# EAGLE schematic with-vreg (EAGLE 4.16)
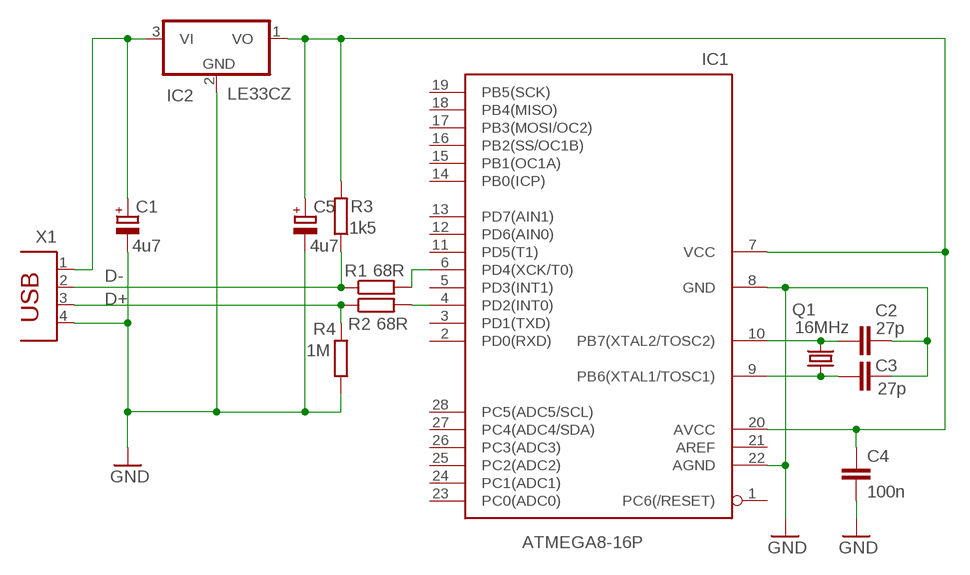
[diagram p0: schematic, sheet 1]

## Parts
C1  4u7  CPOL-EUE2-5  [E2-5]
C2  27p  C-EU025-024X044  [C025-024X044]
C3  27p  C-EU025-024X044  [C025-024X044]
C4  100n  C-EU025-024X044  [C025-024X044]
C5  4u7  CPOL-EUE2-5  [E2-5]
IC1  ATMEGA8-16P  [DIL28-3]
IC2  LE33CZ  78L05Z  [TO92]
Q1  16MHz  CRYTALHC49U-V  [HC49U-V]
R1  68R  R-EU_0207/10  [0207/10]
R2  68R  R-EU_0207/10  [0207/10]
R3  1k5  R-EU_0207/10  [0207/10]
R4  1M  R-EU_0207/10  [0207/10]
X1  PN61729  [PN61729]

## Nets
D+: R2.1 R4.2 X1.3
D-: R1.1 R3.1 X1.2
GND: C1.- C2.2 C3.2 C4.2 C5.- IC1.8(GND) IC1.22(AGND) IC2.2(GND) R4.1 X1.4
N$1: IC1.6(PD4(XCK/T0)) R1.2
N$2: IC1.4(PD2(INT0)) R2.2
N$3: C1.+ IC2.3(VI) X1.1
N$9: C3.1 IC1.9(PB6(XTAL1/TOSC1)) Q1.1
N$10: C2.1 IC1.10(PB7(XTAL2/TOSC2)) Q1.2
VCC: C4.1 C5.+ IC1.7(VCC) IC1.20(AVCC) IC2.1(VO) R3.2
Unconnected: IC1.1(PC6(/RESET)) IC1.2(PD0(RXD)) IC1.3(PD1(TXD)) IC1.5(PD3(INT1)) IC1.11(PD5(T1)) IC1.12(PD6(AIN0)) IC1.13(PD7(AIN1)) IC1.14(PB0(ICP)) IC1.15(PB1(OC1A)) IC1.16(PB2(SS/OC1B)) IC1.17(PB3(MOSI/OC2)) IC1.18(PB4(MISO)) IC1.19(PB5(SCK)) IC1.21(AREF) IC1.23(PC0(ADC0)) IC1.24(PC1(ADC1)) IC1.25(PC2(ADC2)) IC1.26(PC3(ADC3)) IC1.27(PC4(ADC4/SDA)) IC1.28(PC5(ADC5/SCL))

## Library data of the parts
C1 C5 = rcl:CPOL-EU: POLARIZED CAPACITOR, European symbol
C2-C4 = rcl:C-EU: CAPACITOR, European symbol
IC1 = avr:ATMEGA8*P: MICROCONTROLLER 8 Kbytes FLASH 1 kbytes SRAM 512 bytes EEPROM USART 4-channel 10 bit ADC 2-channel 8 bit ADC
IC2 = linear:78*: Positive VOLTAGE REGULATOR Source: http://cache.national.com/ds/LM/LM78L05.pdf http://www.fairchildsemi.com/ds/LM/LM7805.pdf
Q1 = crystal:CRYTAL: CRYSTAL
R1-R4 = rcl:R-EU_: RESISTOR, European symbol
X1 = con-berg:PN61729: BERG USB connector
